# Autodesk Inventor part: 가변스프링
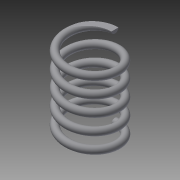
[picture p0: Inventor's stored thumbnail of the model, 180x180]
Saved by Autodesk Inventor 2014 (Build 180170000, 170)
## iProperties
Created: 2019-10
Part Number: 가변스프링
Material: Stainless Steel
Document SubType Name: Modeling
Designer: kh
Density: 8.08 g/cm^3
Appearance: Semi-Polished
Mass: 147.716 g
Surface Area: 124.205 cm^2
Volume: 18.2817 cm^3
Author: kh
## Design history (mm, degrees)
sketch "Sketch1"
  geometry: L1 (0, 0)-(21, 0); L2 (21, 0)-(21, 67.25); L3 (21, 67.25)-(0, 67.25); L4 (0, 67.25)-(0, 0); C1 r 3 at (21, 0)
  constraints: 8 end point, 2 parallel, 1 centre point, 1 coincident, 1 horizontal, 1 perpendicular
  dimensions: "d0" = 42 diameter of L2 L4; "d1" = 67.25 distance of L1.end L2.end (derived); "d2" = 6 diameter of C1
coil "Coil1" sketch "Sketch1" pitch "d3" = 10; turns "d5" = 5; dims "d4" = 67.25 (= d1), "d6" = 0, angle "d7" = 90 deg, angle "d8" = 90 deg, "d9" = 0, "d10" = 0
split "Split1"
workplane "Work Plane1"
split "Split2"
body "Solid1"
other parameters: "d11" = 67.25 (= d1)
